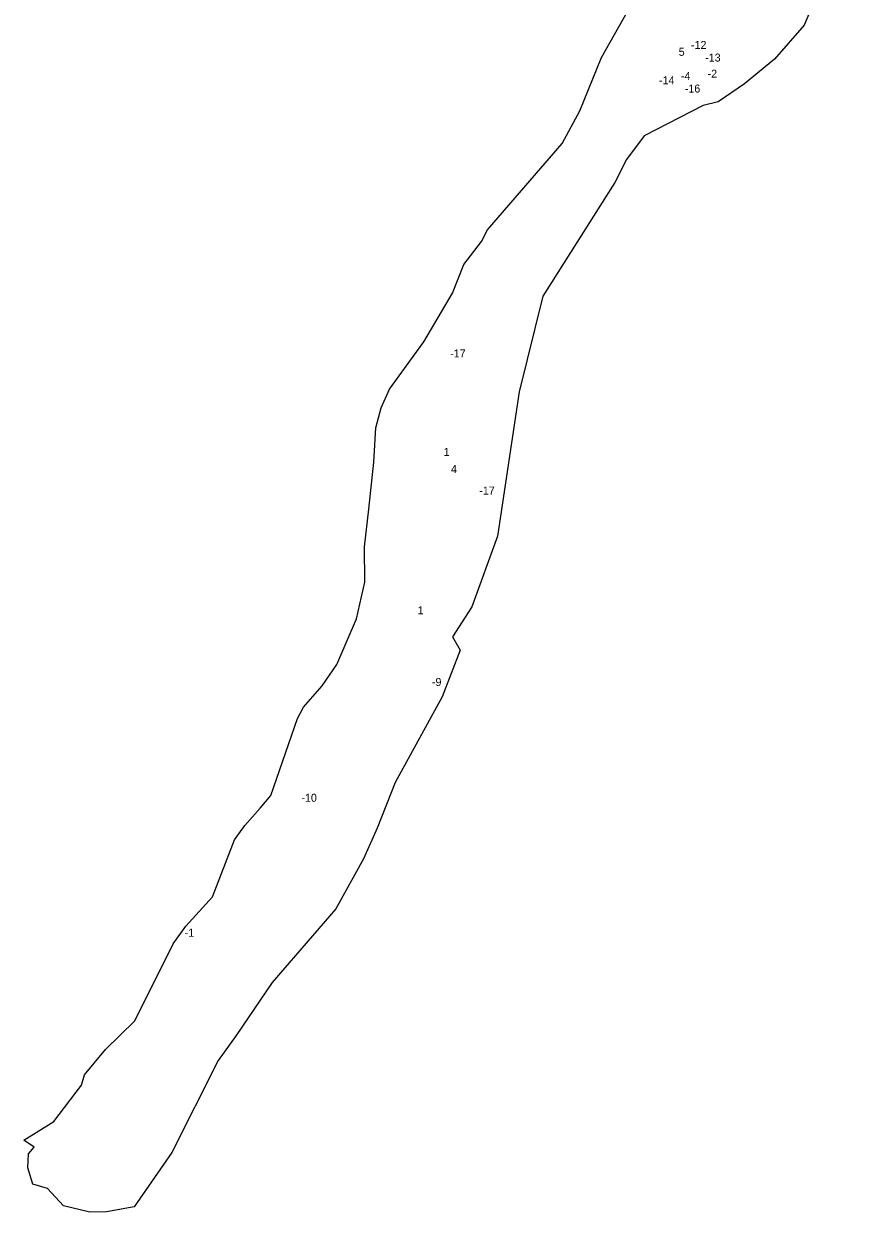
# Model space of a CAD drawing. Extents: x -772526 to -771201, y -966905 to -965268.
# Drawn here: x -772526 to -771960, y -966905 to -966088 of the extents above; entities that cross this region are included whole.
import ezdxf

# ---------------------------------------------------------------- set-up
doc = ezdxf.new("R2010")
doc.units = 0
doc.layers.add('Vrstva 13', color=7, linetype='Continuous')
doc.layers.add('Vrstva 24', color=7, linetype='Continuous')

msp = doc.modelspace()

# ---------------------------------------------------------------- linework, layer by layer
at = {"layer": 'Vrstva 13'}
for p, q in [((-771959.84, -966018.67), (-771989.42, -966088.98)), ((-772128.73, -966111.16), (-772107.87, -966074.47)), ((-771989.42, -966088.98), (-772009.92, -966112.41)), ((-772143.59, -966147.85), (-772128.73, -966111.16)), ((-772009.92, -966112.41), (-772030.42, -966129.4)), ((-772030.42, -966129.4), (-772048.57, -966141.7)), ((-772048.57, -966141.7), (-772058.82, -966144.34)), ((-772155.89, -966170.41), (-772143.59, -966147.85)), ((-772058.82, -966144.34), (-772099.53, -966165.14)), ((-772099.53, -966165.14), (-772111.53, -966181.25)), ((-772207.13, -966229.58), (-772155.89, -966170.41)), ((-772111.53, -966181.25), (-772119.73, -966197.08)), ((-772119.73, -966197.08), (-772169.22, -966275.3)), ((-772211.23, -966237.78), (-772207.13, -966229.58)), ((-772223.53, -966253.6), (-772211.23, -966237.78)), ((-772231.14, -966273.23), (-772223.53, -966253.6)), ((-772251.05, -966306.63), (-772231.14, -966273.23)), ((-772169.22, -966275.3), (-772185.33, -966340.92)), ((-772274.48, -966339.14), (-772251.05, -966306.63)), ((-772280.33, -966352.03), (-772274.48, -966339.14)), ((-772185.33, -966340.92), (-772200.26, -966440.23)), ((-772283.85, -966365.8), (-772280.33, -966352.03)), ((-772285.31, -966389.24), (-772283.85, -966365.8)), ((-772288.83, -966421.75), (-772285.31, -966389.24)), ((-772291.75, -966447.53), (-772288.83, -966421.75)), ((-772200.26, -966440.23), (-772217.83, -966488.86)), ((-772291.46, -966471.85), (-772291.75, -966447.53)), ((-772297.32, -966497.05), (-772291.46, -966471.85)), ((-772217.83, -966488.86), (-772231.3, -966509.36)), ((-772310.79, -966528.39), (-772297.32, -966497.05)), ((-772231.3, -966509.36), (-772226.03, -966518.44)), ((-772226.03, -966518.44), (-772238.32, -966550.66)), ((-772320.75, -966543.04), (-772310.79, -966528.39)), ((-772333.63, -966557.69), (-772320.75, -966543.04)), ((-772238.32, -966550.66), (-772270.54, -966609.55)), ((-772337.73, -966565.6), (-772333.63, -966557.69)), ((-772356.18, -966618.33), (-772337.73, -966565.6)), ((-772270.54, -966609.55), (-772283.13, -966640.89)), ((-772363.5, -966627.12), (-772356.18, -966618.33)), ((-772374.04, -966639.13), (-772363.5, -966627.12)), ((-772381.08, -966648.79), (-772374.04, -966639.13)), ((-772283.13, -966640.89), (-772292.5, -966661.99)), ((-772396.31, -966688.05), (-772381.08, -966648.79)), ((-772292.5, -966661.99), (-772311.54, -966696.26)), ((-772414.46, -966708.26), (-772396.31, -966688.05)), ((-772311.54, -966696.26), (-772355.17, -966746.94)), ((-772423.25, -966720.27), (-772414.46, -966708.26)), ((-772449.61, -966773.29), (-772423.25, -966720.27)), ((-772355.17, -966746.94), (-772380.06, -966783.27)), ((-772469.81, -966792.92), (-772449.61, -966773.29)), ((-772380.06, -966783.27), (-772392.36, -966800.55)), ((-772484.16, -966810.5), (-772469.81, -966792.92)), ((-772392.36, -966800.55), (-772424.27, -966863.82)), ((-772486.21, -966817.53), (-772484.16, -966810.5)), ((-772505.21, -966842.39), (-772486.21, -966817.53)), ((-772526, -966855.28), (-772505.21, -966842.39)), ((-772518.93, -966860.08), (-772526, -966855.28)), ((-772522.66, -966864.7), (-772518.93, -966860.08)), ((-772523.24, -966874.36), (-772522.66, -966864.7)), ((-772424.27, -966863.82), (-772450.04, -966901.03)), ((-772519.73, -966885.49), (-772523.24, -966874.36)), ((-772509.77, -966888.42), (-772519.73, -966885.49)), ((-772498.65, -966900.43), (-772509.77, -966888.42)), ((-772480.49, -966904.83), (-772498.65, -966900.43)), ((-772450.04, -966901.03), (-772469.07, -966904.54)), ((-772469.07, -966904.54), (-772480.49, -966904.83))]:
    msp.add_line(p, q, dxfattribs=at)

# ---------------------------------------------------------------- texts
at = {"layer": 'Vrstva 24'}
for s, p in [('-12', (-772067.261, -966105.38)), ('5', (-772075.7, -966110.08)), ('-13', (-772057.521, -966114.05)), ('-14', (-772089.28, -966129.67)), ('-4', (-772074.202, -966126.68)), ('-2', (-772055.842, -966125.12)), ('-16', (-772071.51, -966135.34)), ('-17', (-772232.842, -966317.37)), ('1', (-772237.32, -966385.04)), ('4', (-772232.29, -966396.83)), ('-17', (-772212.812, -966411.6)), ('1', (-772255.2, -966493.9)), ('-9', (-772245.392, -966543.18)), ('-10', (-772335.099, -966622.72)), ('-1', (-772415.361, -966715.54))]:
    msp.add_text(s, height=5.5, dxfattribs=at).set_placement(p)

doc.saveas('drawing.dxf')
